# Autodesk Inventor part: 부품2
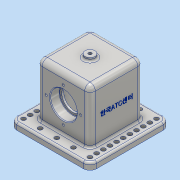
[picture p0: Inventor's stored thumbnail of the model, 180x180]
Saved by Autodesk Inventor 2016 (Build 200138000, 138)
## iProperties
Created: 2018-11
Part Number: 부품2
Material: 알루미늄 6061
Document SubType Name: Modeling
Designer: PC-2
Density: 2.7 g/cm^3
Appearance: 알루미늄 - 평지
Author: PC-2
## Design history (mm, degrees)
sketch "스케치1"
  geometry: L1 (-60, 60)-(60, 60); L2 (60, 60)-(60, -60); L3 (60, -60)-(-60, -60); L4 (-60, -60)-(-60, 60); L5 (-60, 60)-(60, -60); L6 (60, 60)-(-60, -60); 1 further point
  constraints: 12 end point, 2 midpoint, 2 parallel, 1 horizontal, 1 perpendicular
  dimensions: "d0" = 120 distance of L1.start L1.end; "d1" = 120 distance of L3.end L1.start
extrude "돌출1" new body sketch "스케치1" distance "d2" = 10; taper "d3" = 0 deg
sketch "스케치2"
  geometry: L1 (-40, 40)-(40, 40); L2 (40, 40)-(40, -40); L3 (40, -40)-(-40, -40); L4 (-40, -40)-(-40, 40); L5 (-40, 40)-(40, -40); L6 (40, 40)-(-40, -40); 1 further point
  constraints: 12 end point, 2 midpoint, 2 parallel, 1 horizontal, 1 perpendicular
  dimensions: "d4" = 80 distance of L1.start L1.end; "d5" = 80 distance of L3.end L1.start
extrude "돌출2" join sketch "스케치2" distance "d6" = 80; taper "d7" = 0 deg
sketch "스케치3"
  geometry: L1 (23, -30)-(-23, -30); L2 (-23, -30)-(-23, 30); L3 (-23, 30)-(23, 30); L4 (23, 30)-(23, -30); L5 (23, -30)-(-23, 30); L6 (-23, -30)-(23, 30); 1 further point
  constraints: 12 end point, 2 midpoint, 2 parallel, 1 horizontal, 1 perpendicular
  dimensions: "d8" = 46 distance of L1.start L1.end; "d9" = 60 distance of L3.end L1.start
extrude "돌출3" cut sketch "스케치3" distance "d10" = 80; taper "d11" = 0 deg
sketch "스케치4"
  geometry: L1 (10, 100)-(10, -20) reference; 2 further points
  dimensions: "d12" = 48 distance from line of point (-38, 40) L1
hole "구멍1" sketch "스케치4" at (-38, 40) diameter "d13" = 33; stored, may be unused: countersink angle "d17" = 90 deg, drill point angle "d19" = 0 deg; dims "d14" = 6, "d15" = 40, "d16" = 14, "d18" = 3
node "작업 평면1"
sketch "스케치5"
  geometry: C1 r 7.5 at (0, 0); 1 further point
  constraints: 1 centre point, 1 coincident
  dimensions: "d21" = 15 diameter of C1
extrude "돌출4" join sketch "스케치5" stored distance "d22" = 80; taper "d23" = 0 deg
fillet "모깎기1" dims "d24" = 10
hole "구멍2" diameter "d27" = 4.917; stored, may be unused: countersink angle "d31" = 90 deg, drill point angle "d33" = 0 deg; dims "d28" = 20, "d29" = 4, "d30" = 2, "d32" = 25.1, "d92" = 10, "d93" = 10
sketch "스케치6" dims "d34" = 52
  geometry: C1 r 20 at (-38, 40) reference; 3 further points
  constraints: 1 coincident, 1 horizontal alignment, 2 other
hole "구멍3" sketch "스케치6" at (-64, 40) diameter "d35" = 3.242; stored, may be unused: countersink angle "d39" = 90 deg, drill point angle "d41" = 118 deg; dims "d36" = 8, "d37" = 4, "d38" = 2, "d40" = 10
sketch "스케치7"
  geometry: L1 (-23, 30)-(-23, -30) reference; L2 (-23, -30)-(23, -30) reference; 2 further points
  dimensions: "d45" = 50 horizontal distance of point (-50, -50) point (0, 0); "d46" = 50 horizontal distance of point (-50, -50) point (0, 0)
hole "구멍4" sketch "스케치7" at (-50, -50) diameter "d47" = 6.6; stored, may be unused: countersink angle "d51" = 90 deg, drill point angle "d53" = 0 deg; dims "d48" = 8, "d49" = 4, "d50" = 2, "d52" = 10
sketch "스케치8"
  geometry: C1 r 3.3 at (-50, -50) reference; 11 further points
  constraints: 1 vertical alignment
  dimensions: "d54" = 10 distance of C1.centre point (-40, -50); "d55" = 10 distance of point (-30, -50) point (-40, -50); "d56" = 10 distance of point (-20, -50) point (-30, -50); "d57" = 10 distance of point (-20, -50) point (-10, -50); "d59" = 10 distance of point (0, -50) point (10, -50); "d60" = 10 distance of point (10, -50) point (20, -50); "d61" = 10 distance of point (20, -50) point (30, -50); "d62" = 10 distance of point (40, -50) point (30, -50); "d63" = 10 distance of point (40, -50) point (50, -50)
hole "구멍5" sketch "스케치8" at (-40, -50), (-30, -50), (-20, -50), (0, -50), (10, -50), (20, -50), (40, -50), (50, -50), (-10, -50), (30, -50) diameter "d64" = 6.6; stored, may be unused: countersink angle "d68" = 90 deg, drill point angle "d70" = 0 deg; dims "d65" = 8, "d66" = 4, "d67" = 2, "d69" = 10
sketch "스케치9"
  geometry: C1 r 3.3 at (-50, 50) reference; C2 r 3.3 at (-50, -50) reference; 4 further points
  constraints: 1 horizontal alignment
  dimensions: "d71" = 25 distance of C1.centre point (-50, 25); "d72" = 25 distance of C2.centre point (-50, -25)
hole "구멍6" sketch "스케치9" at (-50, 0), (-50, 25), (-50, -25) diameter "d73" = 6.6; stored, may be unused: countersink angle "d77" = 90 deg, drill point angle "d79" = 0 deg; dims "d74" = 8, "d75" = 4, "d76" = 2, "d78" = 10
sketch "스케치10"
  geometry: L1 (-10, 10)-(90, 10) reference; 3 further points
  constraints: 1 midpoint, 1 vertical alignment, 1 other
  dimensions: "d80" = 48 distance from line of L1 point (40, -38)
feature "엠보싱1" sketch "스케치10" dims "d0" = 120, "d1" = 120, "d81" = 0.5, "d82" = 0
fillet "모깎기2" dims "d83" = 8
fillet "모깎기3" dims "d84" = 8
fillet "모깎기4" dims "d85" = 3
chamfer "모따기1" distance "d86" = 1; stored, may be unused: second distance "d87" = 2, angle "d88" = 45 deg
fillet "모깎기5" dims "d89" = 0.6
fillet "모깎기6" dims "d90" = 3
node "솔리드1"
mirror "대칭1"
pattern_circular "원형 패턴1" dims angle "d43" = 360 deg
mirror "대칭2"
mirror "대칭3"
mirror "대칭4"
other parameters: "d20" = 95
